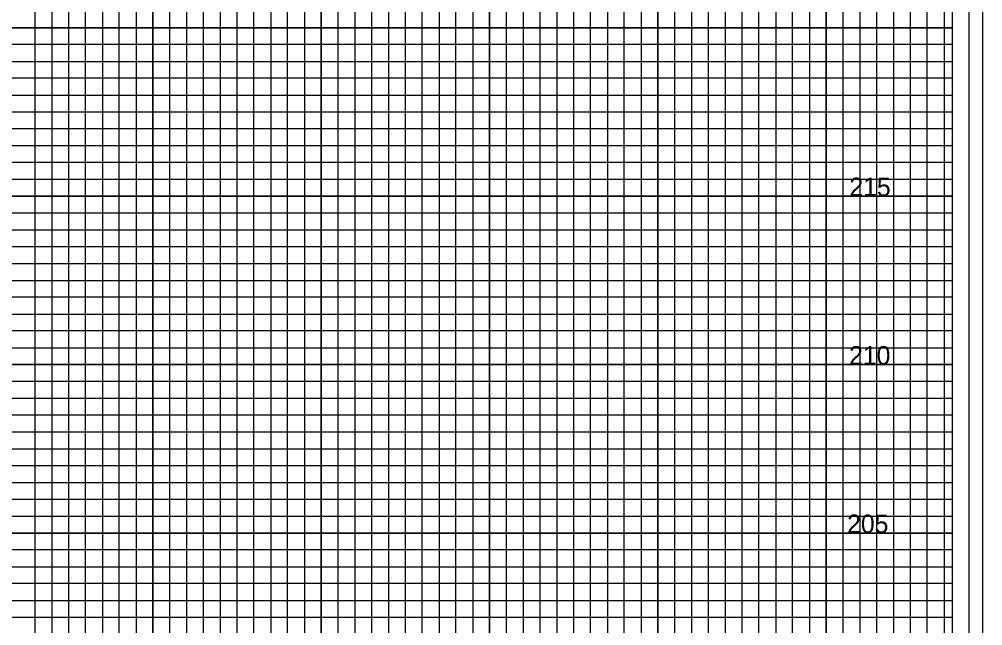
# Model space of a CAD drawing. Extents: x -4 to 103, y -2 to 351.
# Drawn here: x 74.78 to 103.4, y 315.55 to 333.55 of the extents above; entities that cross this region are included whole.
import ezdxf

# ---------------------------------------------------------------- set-up
doc = ezdxf.new("R2010")
doc.units = 0
for name, color, linetype in [('Old_Level_10', 7, 'Continuous'), ('Old_Level_4', 7, 'Continuous'), ('Old_Level_5', 7, 'Continuous'), ('Old_Level_6', 7, 'Continuous'), ('Old_Level_8', 7, 'Continuous'), ('Prop XS Finish Grade', 7, 'Continuous'), ('Prop XS SE Text', 7, 'Continuous')]:
    doc.layers.add(name, color=color, linetype=linetype)

msp = doc.modelspace()

# ---------------------------------------------------------------- linework, layer by layer
at = {"layer": 'Old_Level_10'}
for p, q in [((91.25, 283.3), (91.25, 346.725)), ((93.75, 283.3), (93.75, 346.725)), ((96.25, 283.3), (96.25, 346.725)), ((98.75, 283.3), (98.75, 346.725)), ((101.25, 283.3), (101.25, 346.725)), ((76.25, 283.3), (76.25, 345.3)), ((78.75, 283.3), (78.75, 345.3)), ((81.25, 283.3), (81.25, 345.3)), ((83.75, 283.3), (83.75, 345.3)), ((86.25, 283.3), (86.25, 345.3)), ((88.75, 283.3), (88.75, 345.3)), ((0, 333.3), (102.5, 333.3)), ((0, 330.8), (102.5, 330.8)), ((0, 328.3), (102.5, 328.3)), ((0, 325.8), (102.5, 325.8)), ((0, 323.3), (102.5, 323.3)), ((0, 320.8), (102.5, 320.8)), ((0, 318.3), (102.5, 318.3)), ((0, 315.8), (102.5, 315.8))]:
    msp.add_line(p, q, dxfattribs=at)
at = {"layer": 'Old_Level_4'}
for points in [[(90.25, 283.3), (90.25, 346.725), (90.75, 346.725), (90.75, 283.3)], [(91.75, 283.3), (91.75, 346.725), (92.25, 346.725), (92.25, 283.3)], [(92.75, 283.3), (92.75, 346.725), (93.25, 346.725), (93.25, 283.3)], [(94.25, 283.3), (94.25, 346.725), (94.75, 346.725), (94.75, 283.3)], [(95.25, 283.3), (95.25, 346.725), (95.75, 346.725), (95.75, 283.3)], [(96.75, 283.3), (96.75, 346.725), (97.25, 346.725), (97.25, 283.3)], [(97.75, 283.3), (97.75, 346.725), (98.25, 346.725), (98.25, 283.3)], [(99.25, 283.3), (99.25, 346.725), (99.75, 346.725), (99.75, 283.3)], [(100.25, 283.3), (100.25, 346.725)], [(100.25, 346.725), (100.75, 346.725), (100.75, 283.3), (101.75, 283.3), (101.75, 346.725), (102.25, 346.725), (102.25, 283.3)], [(75.25, 283.3), (75.25, 345.3), (75.75, 345.3), (75.75, 283.3)], [(76.75, 283.3), (76.75, 345.3), (77.25, 345.3), (77.25, 283.3)], [(77.75, 283.3), (77.75, 345.3), (78.25, 345.3), (78.25, 283.3)], [(79.25, 283.3), (79.25, 345.3), (79.75, 345.3), (79.75, 283.3)], [(80.25, 283.3), (80.25, 345.3), (80.75, 345.3), (80.75, 283.3)], [(81.75, 283.3), (81.75, 345.3), (82.25, 345.3), (82.25, 283.3)], [(82.75, 283.3), (82.75, 345.3), (83.25, 345.3), (83.25, 283.3)], [(84.25, 283.3), (84.25, 345.3), (84.75, 345.3), (84.75, 283.3)], [(85.25, 283.3), (85.25, 345.3), (85.75, 345.3), (85.75, 283.3)], [(86.75, 283.3), (86.75, 345.3), (87.25, 345.3), (87.25, 283.3)], [(87.75, 283.3), (87.75, 345.3), (88.25, 345.3), (88.25, 283.3)], [(89.25, 283.3), (89.25, 345.3), (89.75, 345.3), (89.75, 283.3)], [(0, 332.3), (102.5, 332.3), (102.5, 332.8), (0, 332.8)], [(0, 331.3), (102.5, 331.3), (102.5, 331.8), (0, 331.8)], [(0, 329.8), (102.5, 329.8), (102.5, 330.3), (0, 330.3)], [(0, 328.8), (102.5, 328.8), (102.5, 329.3), (0, 329.3)], [(0, 327.3), (102.5, 327.3), (102.5, 327.8), (0, 327.8)], [(0, 326.3), (102.5, 326.3), (102.5, 326.8), (0, 326.8)], [(0, 324.8), (102.5, 324.8), (102.5, 325.3), (0, 325.3)], [(0, 323.8), (102.5, 323.8), (102.5, 324.3), (0, 324.3)], [(0, 322.3), (102.5, 322.3), (102.5, 322.8), (0, 322.8)], [(0, 321.3), (102.5, 321.3), (102.5, 321.8), (0, 321.8)], [(0, 319.8), (102.5, 319.8), (102.5, 320.3), (0, 320.3)], [(0, 318.8), (102.5, 318.8), (102.5, 319.3), (0, 319.3)], [(0, 317.3), (102.5, 317.3), (102.5, 317.8), (0, 317.8)], [(0, 316.3), (102.5, 316.3), (102.5, 316.8), (0, 316.8)]]:
    msp.add_lwpolyline(points, dxfattribs=at)
at = {"layer": 'Old_Level_5'}
msp.add_lwpolyline([(103.4, 350.7), (-3.5, 350.7), (-3.5, 280.875), (103.4, 280.875)], close=True, dxfattribs=at)
at = {"layer": 'Old_Level_6'}
msp.add_lwpolyline([(102.5, 348.3), (0, 348.3), (0, 283.3), (102.5, 283.3)], close=True, dxfattribs=at)
at = {"layer": 'Old_Level_8'}
for points in [[(91.25, 283.3), (91.25, 346.725), (93.75, 346.725), (93.75, 283.3)], [(96.25, 283.3), (96.25, 346.725), (98.75, 346.725), (98.75, 283.3)], [(101.25, 283.3), (101.25, 346.725)], [(76.25, 283.3), (76.25, 345.3), (78.75, 345.3), (78.75, 283.3)], [(81.25, 283.3), (81.25, 345.3), (83.75, 345.3), (83.75, 283.3)], [(86.25, 283.3), (86.25, 345.3), (88.75, 345.3), (88.75, 283.3)], [(0, 330.8), (102.5, 330.8), (102.5, 333.3), (0, 333.3)], [(0, 325.8), (102.5, 325.8), (102.5, 328.3), (0, 328.3)], [(0, 320.8), (102.5, 320.8), (102.5, 323.3), (0, 323.3)], [(0, 315.8), (102.5, 315.8), (102.5, 318.3), (0, 318.3)]]:
    msp.add_lwpolyline(points, dxfattribs=at)
at = {"layer": 'Prop XS SE Text'}
msp.add_lwpolyline([(103, 349.3), (-2.8, 349.3), (-2.8, 282.3), (103, 282.3)], close=True, dxfattribs=at)

# ---------------------------------------------------------------- texts
at = {"layer": 'Prop XS Finish Grade'}
for s, p in [('215', (99.4383, 328.3)), ('210', (99.4296, 323.3)), ('205', (99.3724, 318.3))]:
    msp.add_text(s, height=0.55, dxfattribs=at).set_placement(p)

doc.saveas('drawing.dxf')
